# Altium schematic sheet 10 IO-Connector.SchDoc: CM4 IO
size 420 x 297 mm; Page Create Date: March  8, 1995; Page Number: 10; Page Size: A3; Comment: radxa_1010; Page Count: 19; RevCode: V1.10; Doc: 10 IO-Connector; DsnPath: D:\WMS\黄工\[RC126]CM4_IO_V1.10\[RC126]_V1.10\CM4 IO_V1.10.DSN; SchematicName: CM4 IO V1.10; PageName: 10 IO-Connector; PageSize: A3; TopSchematic: True
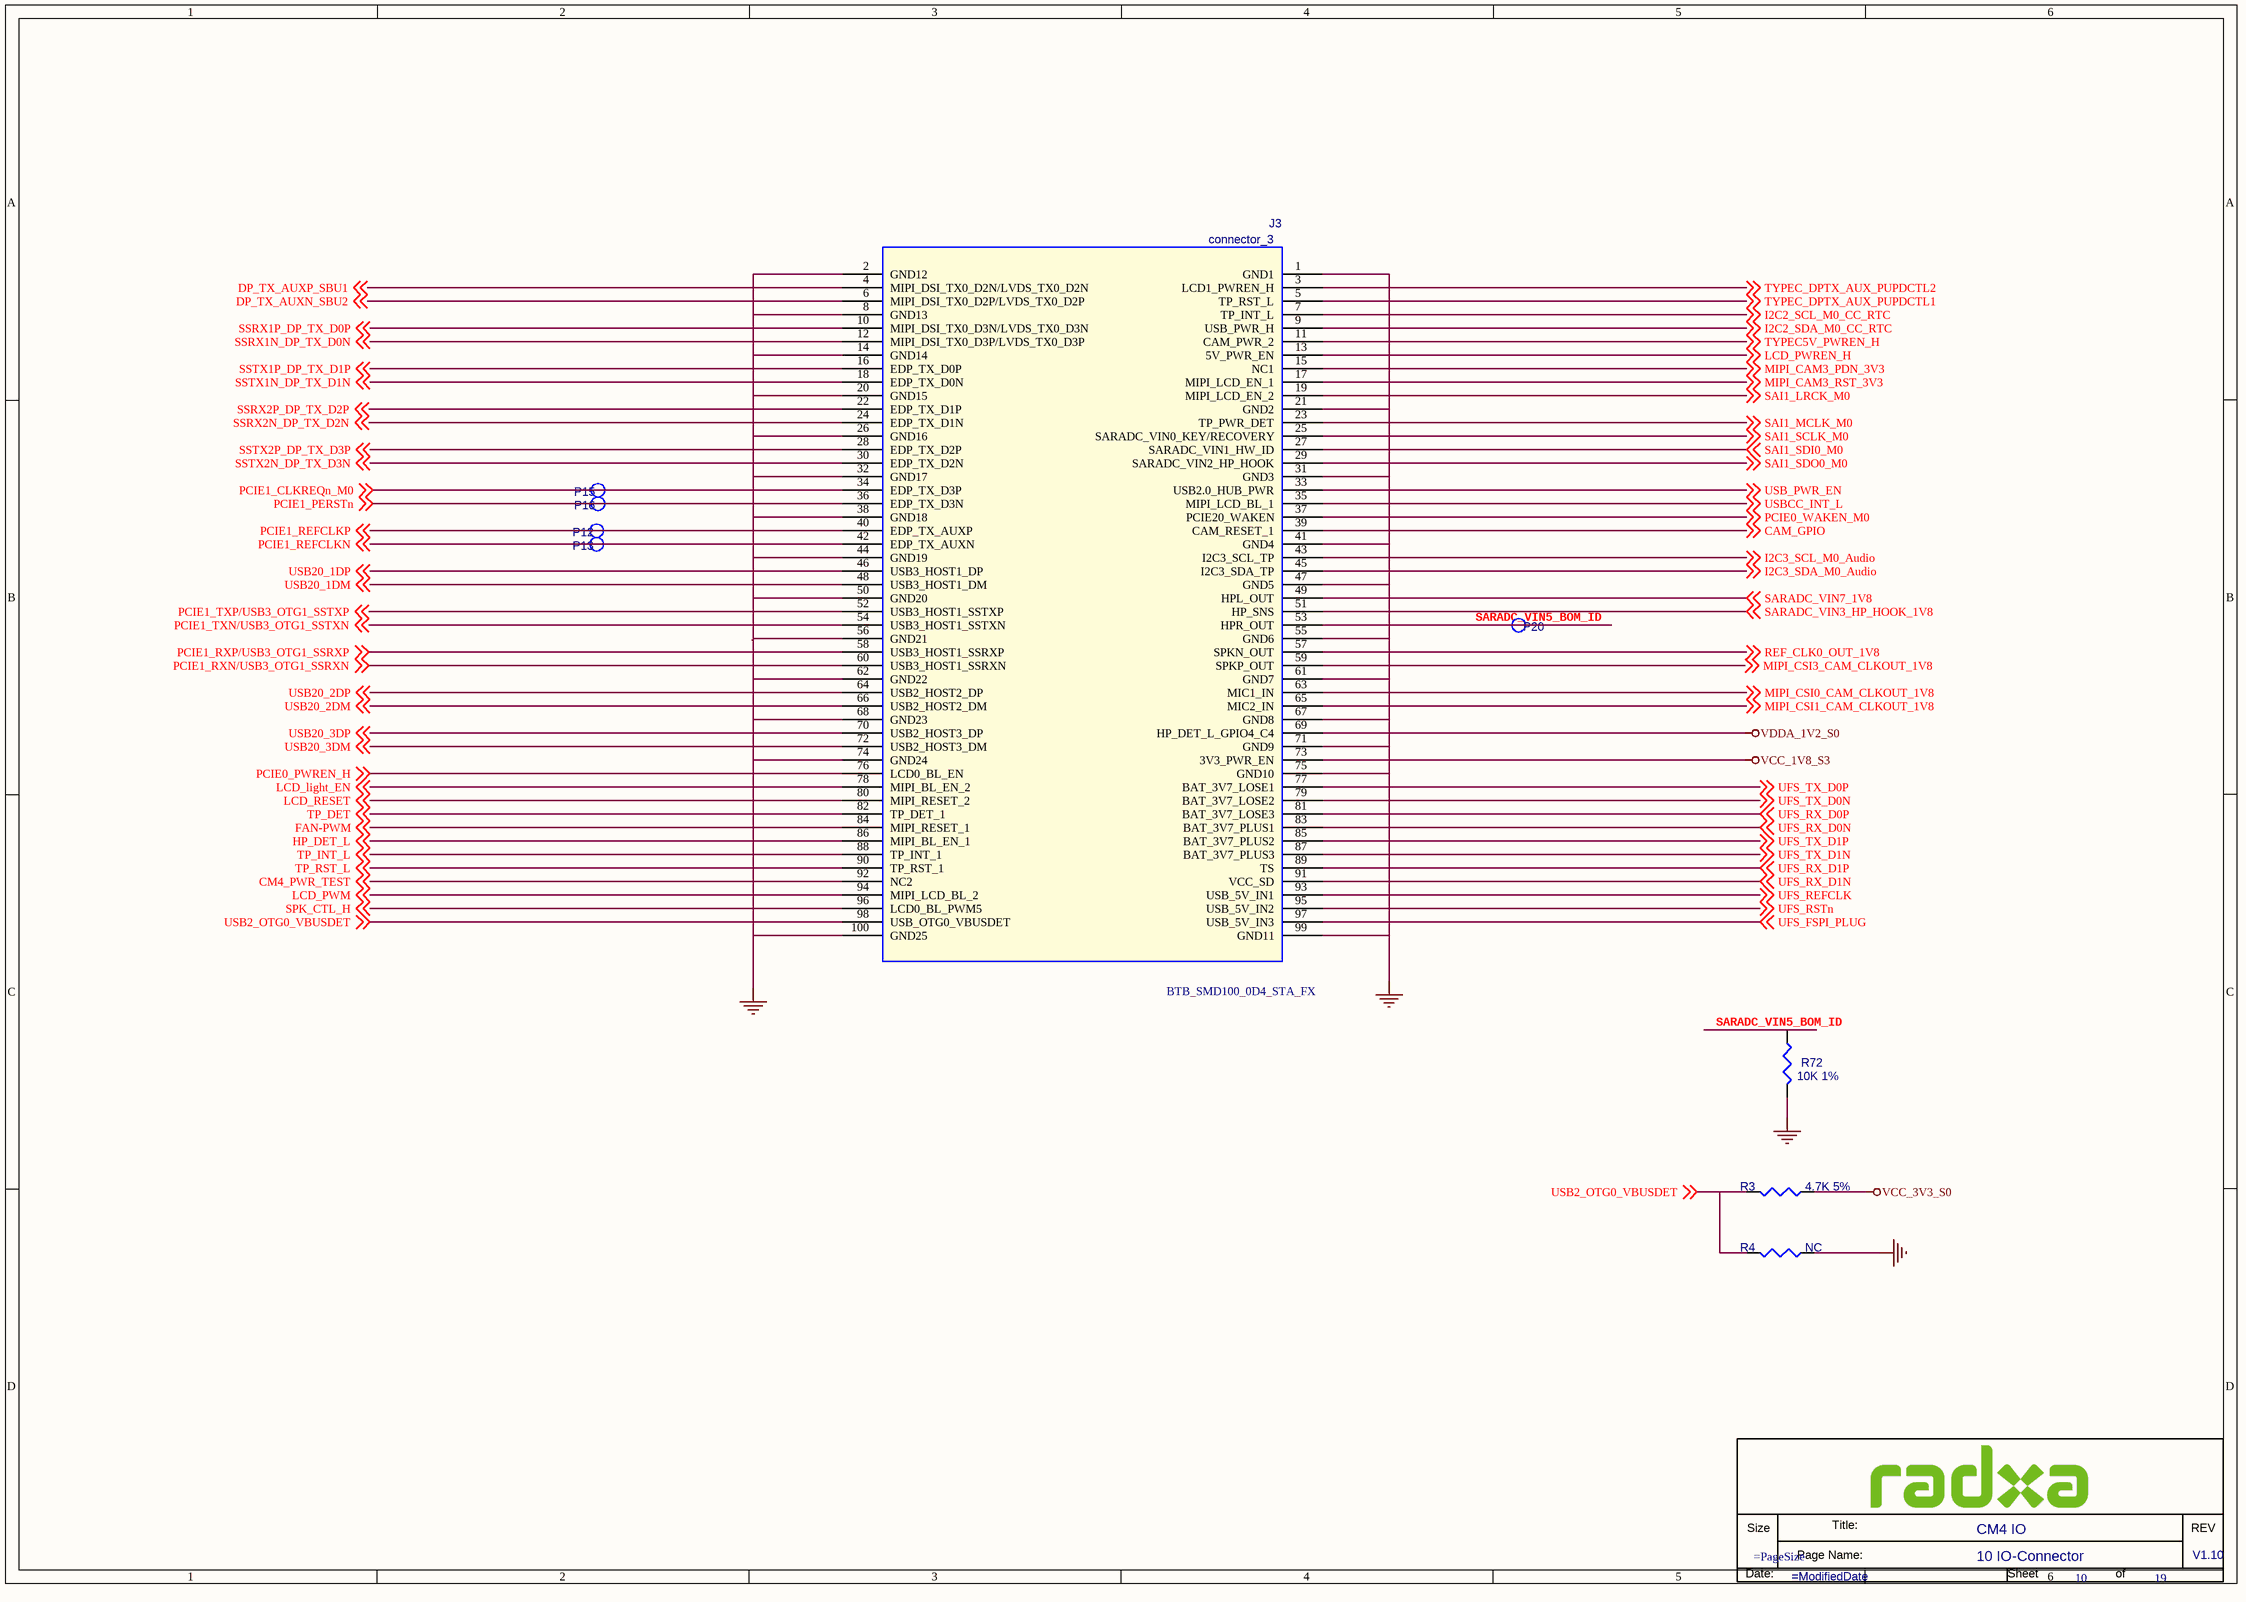
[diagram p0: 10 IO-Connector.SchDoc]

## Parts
*  Doc: 10 IO-Connector  RevCode: V1.10  Title: CM4 IO  Page Number: 10  Page Count: 19  (hidden comment: radxa_1010)  (graphical)
J3  connector_3  [BTB_SMD100_0D4_STA_FX]
P12  TEST  [TEST]  (value not drawn)
P13  TEST  [TEST]  (value not drawn)
P15  TEST  [TEST]  (value not drawn)
P16  TEST  [TEST]  (value not drawn)
P20  TEST  [TEST]  (value not drawn)
R3  4.7K 5%  [R0402]
R4  NC  [R0402]
R72  10K 1%  [R0402]

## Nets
GND: J3.1(GND1) J3.2(GND12) J3.8(GND13) J3.14(GND14) J3.20(GND15) J3.21(GND2) J3.26(GND16) J3.31(GND3) J3.32(GND17) J3.38(GND18) J3.41(GND4) J3.44(GND19) J3.47(GND5) J3.50(GND20) J3.55(GND6) J3.56(GND21) J3.61(GND7) J3.62(GND22) J3.67(GND8) J3.68(GND23) J3.71(GND9) J3.74(GND24) J3.75(GND10) J3.99(GND11) J3.100(GND25) R4.2 R72.2
VCC_1V8_S3: J3.73(3V3_PWR_EN)
VCC_3V3_S0: R3.2
VDDA_1V2_S0: J3.69(HP_DET_L_GPIO4_C4)
CAM_GPIO: J3.39(CAM_RESET_1) ; off-sheet CAM_GPIO
CM4_PWR_TEST: J3.92(NC2) ; off-sheet CM4_PWR_TEST
DP_TX_AUXN_SBU2: J3.6(MIPI_DSI_TX0_D2P/LVDS_TX0_D2P) ; off-sheet DP_TX_AUXN_SBU2
DP_TX_AUXP_SBU1: J3.4(MIPI_DSI_TX0_D2N/LVDS_TX0_D2N) ; off-sheet DP_TX_AUXP_SBU1
FAN-PWM: J3.84(MIPI_RESET_1) ; off-sheet FAN-PWM
HP_DET_L: J3.86(MIPI_BL_EN_1) ; off-sheet HP_DET_L
I2C2_SCL_M0_CC_RTC: J3.7(TP_INT_L) ; off-sheet I2C2_SCL_M0_CC_RTC
I2C2_SDA_M0_CC_RTC: J3.9(USB_PWR_H) ; off-sheet I2C2_SDA_M0_CC_RTC
I2C3_SCL_M0_Audio: J3.43(I2C3_SCL_TP) ; off-sheet I2C3_SCL_M0_Audio
I2C3_SDA_M0_Audio: J3.45(I2C3_SDA_TP) ; off-sheet I2C3_SDA_M0_Audio
LCD_light_EN: J3.78(MIPI_BL_EN_2) ; off-sheet LCD_light_EN
LCD_PWM: J3.94(MIPI_LCD_BL_2) ; off-sheet LCD_PWM
LCD_PWREN_H: J3.13(5V_PWR_EN) ; off-sheet LCD_PWREN_H
LCD_RESET: J3.80(MIPI_RESET_2) ; off-sheet LCD_RESET
MIPI_CAM3_PDN_3V3: J3.15(NC1) ; off-sheet MIPI_CAM3_PDN_3V3
MIPI_CAM3_RST_3V3: J3.17(MIPI_LCD_EN_1) ; off-sheet MIPI_CAM3_RST_3V3
MIPI_CSI0_CAM_CLKOUT_1V8: J3.63(MIC1_IN) ; off-sheet MIPI_CSI0_CAM_CLKOUT_1V8
MIPI_CSI1_CAM_CLKOUT_1V8: J3.65(MIC2_IN) ; off-sheet MIPI_CSI1_CAM_CLKOUT_1V8
MIPI_CSI3_CAM_CLKOUT_1V8: J3.59(SPKP_OUT) ; off-sheet MIPI_CSI3_CAM_CLKOUT_1V8
PCIE0_PWREN_H: J3.76(LCD0_BL_EN) ; off-sheet PCIE0_PWREN_H
PCIE0_WAKEN_M0: J3.37(PCIE20_WAKEN) ; off-sheet PCIE0_WAKEN_M0
PCIE1_CLKREQn_M0: J3.34(EDP_TX_D3P) P15.1 ; off-sheet PCIE1_CLKREQn_M0
PCIE1_PERSTn: J3.36(EDP_TX_D3N) P16.1 ; off-sheet PCIE1_PERSTn
PCIE1_REFCLKN: J3.42(EDP_TX_AUXN) P13.1 ; off-sheet PCIE1_REFCLKN
PCIE1_REFCLKP: J3.40(EDP_TX_AUXP) P12.1 ; off-sheet PCIE1_REFCLKP
PCIE1_RXN/USB3_OTG1_SSRXN: J3.60(USB3_HOST1_SSRXN) ; off-sheet PCIE1_RXN/USB3_OTG1_SSRXN
PCIE1_RXP/USB3_OTG1_SSRXP: J3.58(USB3_HOST1_SSRXP) ; off-sheet PCIE1_RXP/USB3_OTG1_SSRXP
PCIE1_TXN/USB3_OTG1_SSTXN: J3.54(USB3_HOST1_SSTXN) ; off-sheet PCIE1_TXN/USB3_OTG1_SSTXN
PCIE1_TXP/USB3_OTG1_SSTXP: J3.52(USB3_HOST1_SSTXP) ; off-sheet PCIE1_TXP/USB3_OTG1_SSTXP
REF_CLK0_OUT_1V8: J3.57(SPKN_OUT) ; off-sheet REF_CLK0_OUT_1V8
SAI1_LRCK_M0: J3.19(MIPI_LCD_EN_2) ; off-sheet SAI1_LRCK_M0
SAI1_MCLK_M0: J3.23(TP_PWR_DET) ; off-sheet SAI1_MCLK_M0
SAI1_SCLK_M0: J3.25(SARADC_VIN0_KEY/RECOVERY) ; off-sheet SAI1_SCLK_M0
SAI1_SDI0_M0: J3.27(SARADC_VIN1_HW_ID) ; off-sheet SAI1_SDI0_M0
SAI1_SDO0_M0: J3.29(SARADC_VIN2_HP_HOOK) ; off-sheet SAI1_SDO0_M0
SARADC_VIN3_HP_HOOK_1V8: J3.51(HP_SNS) ; off-sheet SARADC_VIN3_HP_HOOK_1V8
SARADC_VIN5_BOM_ID: J3.53(HPR_OUT) P20.1 R72.1
SARADC_VIN7_1V8: J3.49(HPL_OUT) ; off-sheet SARADC_VIN7_1V8
SPK_CTL_H: J3.96(LCD0_BL_PWM5) ; off-sheet SPK_CTL_H
SSRX1N_DP_TX_D0N: J3.12(MIPI_DSI_TX0_D3P/LVDS_TX0_D3P) ; off-sheet SSRX1N_DP_TX_D0N
SSRX1P_DP_TX_D0P: J3.10(MIPI_DSI_TX0_D3N/LVDS_TX0_D3N) ; off-sheet SSRX1P_DP_TX_D0P
SSRX2N_DP_TX_D2N: J3.24(EDP_TX_D1N) ; off-sheet SSRX2N_DP_TX_D2N
SSRX2P_DP_TX_D2P: J3.22(EDP_TX_D1P) ; off-sheet SSRX2P_DP_TX_D2P
SSTX1N_DP_TX_D1N: J3.18(EDP_TX_D0N) ; off-sheet SSTX1N_DP_TX_D1N
SSTX1P_DP_TX_D1P: J3.16(EDP_TX_D0P) ; off-sheet SSTX1P_DP_TX_D1P
SSTX2N_DP_TX_D3N: J3.30(EDP_TX_D2N) ; off-sheet SSTX2N_DP_TX_D3N
SSTX2P_DP_TX_D3P: J3.28(EDP_TX_D2P) ; off-sheet SSTX2P_DP_TX_D3P
TP_DET: J3.82(TP_DET_1) ; off-sheet TP_DET
TP_INT_L: J3.88(TP_INT_1) ; off-sheet TP_INT_L
TP_RST_L: J3.90(TP_RST_1) ; off-sheet TP_RST_L
TYPEC5V_PWREN_H: J3.11(CAM_PWR_2) ; off-sheet TYPEC5V_PWREN_H
TYPEC_DPTX_AUX_PUPDCTL1: J3.5(TP_RST_L) ; off-sheet TYPEC_DPTX_AUX_PUPDCTL1
TYPEC_DPTX_AUX_PUPDCTL2: J3.3(LCD1_PWREN_H) ; off-sheet TYPEC_DPTX_AUX_PUPDCTL2
UFS_FSPI_PLUG: J3.97(USB_5V_IN3) ; off-sheet UFS_FSPI_PLUG
UFS_REFCLK: J3.93(USB_5V_IN1) ; off-sheet UFS_REFCLK
UFS_RSTn: J3.95(USB_5V_IN2) ; off-sheet UFS_RSTn
UFS_RX_D0N: J3.83(BAT_3V7_PLUS1) ; off-sheet UFS_RX_D0N
UFS_RX_D0P: J3.81(BAT_3V7_LOSE3) ; off-sheet UFS_RX_D0P
UFS_RX_D1N: J3.91(VCC_SD) ; off-sheet UFS_RX_D1N
UFS_RX_D1P: J3.89(TS) ; off-sheet UFS_RX_D1P
UFS_TX_D0N: J3.79(BAT_3V7_LOSE2) ; off-sheet UFS_TX_D0N
UFS_TX_D0P: J3.77(BAT_3V7_LOSE1) ; off-sheet UFS_TX_D0P
UFS_TX_D1N: J3.87(BAT_3V7_PLUS3) ; off-sheet UFS_TX_D1N
UFS_TX_D1P: J3.85(BAT_3V7_PLUS2) ; off-sheet UFS_TX_D1P
USB2_OTG0_VBUSDET: J3.98(USB_OTG0_VBUSDET) R3.1 R4.1 ; off-sheet USB2_OTG0_VBUSDET
USB20_1DM: J3.48(USB3_HOST1_DM) ; off-sheet USB20_1DM
USB20_1DP: J3.46(USB3_HOST1_DP) ; off-sheet USB20_1DP
USB20_2DM: J3.66(USB2_HOST2_DM) ; off-sheet USB20_2DM
USB20_2DP: J3.64(USB2_HOST2_DP) ; off-sheet USB20_2DP
USB20_3DM: J3.72(USB2_HOST3_DM) ; off-sheet USB20_3DM
USB20_3DP: J3.70(USB2_HOST3_DP) ; off-sheet USB20_3DP
USB_PWR_EN: J3.33(USB2.0_HUB_PWR) ; off-sheet USB_PWR_EN
USBCC_INT_L: J3.35(MIPI_LCD_BL_1) ; off-sheet USBCC_INT_L

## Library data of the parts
J3 = BTB_0: SMD  公座  2*50PIN  180度  21.5*1.85*1.14mm  0.4mm脚距  黑色  DF40C-100DP-0.4V(51)  HRS(广濑)  ROHS; Part Reference: J3; Part Number: A1J01.00021; Temp Coeff: -35℃ to +85℃; Preferred: 6715f349cd0bc5
P12 = TESTPOINT1: Part Reference: P12; PCB Footprint: TP_0R70
P13 = TESTPOINT1: Part Reference: P13; PCB Footprint: TP_0R70
P15 = TESTPOINT1: Part Reference: P15; PCB Footprint: TP_0R70
P16 = TESTPOINT1: Part Reference: P16; PCB Footprint: TP_0R70
P20 = TESTPOINT1: Part Reference: P20; PCB Footprint: TP_0R70
R3 = R: SMD  0201  4.7K  1/20W  ±5%  ROHS; Part Reference: R3; Part Number: A1R01.00014; PCB Footprint: R0201; Temp Coeff: -55℃ to +125℃; Preferred: 6715f349cd0bc5
R4 = R: SMD  0201  4.7K  1/20W  ±5%  ROHS; Part Reference: R4; Part Number: A1R01.00014; PCB Footprint: R0201; Temp Coeff: -55℃ to +125℃; Preferred: 6715f349cd0bc5
R72 = R: SMD  0201  10K  1/20W  ±1%  ROHS; Part Reference: R72; Part Number: A1R01.00060; PCB Footprint: R0201; Temp Coeff: -55℃ to +125℃; Preferred: 6715f349cd0bc5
